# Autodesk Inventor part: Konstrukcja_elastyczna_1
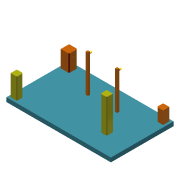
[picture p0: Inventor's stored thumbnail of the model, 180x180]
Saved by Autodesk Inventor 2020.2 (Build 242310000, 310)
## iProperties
Created: 2014-08
Part Number: Konstrukcja_elastyczna_1
Material: Ogólny
Document SubType Name: Modeling
Designer: F.Stasiak
Density: 1 g/cm^3
Appearance: Biały
Catalog Web Link: www.expertbooks.pl
Manager: www.cadconsulting.pl
Company: Fabian Stasiak CAD Consulting
Author: F.Stasiak
Subject: Zbiór ćwiczeń. Autodesk Inventor 2020. Kurs Professional
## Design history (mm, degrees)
sketch "Szkic1"
  geometry: L1 (-1250, 750)-(1250, 750); L2 (1250, 750)-(1250, -750); L3 (1250, -750)-(-1250, -750); L4 (-1250, -750)-(-1250, 750); L5 (-1250, 750)-(1250, -750); L6 (1250, 750)-(-1250, -750); 1 further point
  constraints: 12 end point, 2 midpoint, 2 parallel, 1 horizontal, 1 perpendicular
  dimensions: "d0" = 2500 distance of L2.end L3.end; "d1" = 1500 distance of L1.end L2.end
extrude "Wyciągnięcie proste1" new body sketch "Szkic1" distance "d2" = 100; taper "d3" = 0 deg
sketch "Szkic2"
  geometry: L1 (-1200, -550)-(-1050, -550); L2 (-1050, -550)-(-1050, -700); L3 (-1050, -700)-(-1200, -700); L4 (-1200, -700)-(-1200, -550); L5 (-1200, -550)-(-1050, -700); L6 (-1050, -550)-(-1200, -700); L7 (-1250, -750)-(1250, -750) reference; L8 (-1250, 750)-(-1250, -750) reference; 2 further points
  constraints: 12 end point, 2 midpoint, 2 parallel, 1 horizontal, 1 perpendicular
  dimensions: "d4" = 150 distance of L2.end L3.end; "d5" = 150 distance of L1.end L2.end (= d4); "d6" = 50 distance between parallel lines of L3 L7; "d7" = 50 distance between parallel lines of L8 L4 (= d6)
extrude "Wyciągnięcie proste2" join sketch "Szkic2" distance "d8" = 500; taper "d9" = 0 deg
sketch "Szkic3"
  geometry: L1 (600, -350)-(750, -350); L2 (750, -350)-(750, -200); L3 (750, -200)-(600, -200); L4 (600, -200)-(600, -350); L5 (600, -350)-(750, -200); L6 (750, -350)-(600, -200); L7 (-1250, -750)-(1250, -750) reference; L8 (1250, -750)-(1250, 750) reference; 2 further points
  constraints: 12 end point, 2 midpoint, 2 parallel, 1 horizontal, 1 perpendicular
  dimensions: "d10" = 150 distance of L3.end L2.end; "d11" = 150 distance of L2.end L1.end; "d12" = 400 distance between parallel lines of L7 L1; "d13" = 500 distance between parallel lines of L2 L8
extrude "Wyciągnięcie proste3" join sketch "Szkic3" distance "d14" = 800; taper "d15" = 0 deg
sketch "Szkic4"
  geometry: L1 (-1200, 700)-(-1000, 700); L2 (-1000, 700)-(-1000, 500); L3 (-1000, 500)-(-1200, 500); L4 (-1200, 500)-(-1200, 700); L5 (-1200, 700)-(-1000, 500); L6 (-1000, 700)-(-1200, 500); L7 (-1250, 750)-(-1250, -750) reference; L8 (1250, 750)-(-1250, 750) reference; 2 further points
  constraints: 12 end point, 2 midpoint, 2 parallel, 1 horizontal, 1 perpendicular
  dimensions: "d16" = 200 distance of L2.end L3.end; "d17" = 200 distance of L1.end L2.end; "d18" = 50 distance between parallel lines of L7 L4; "d19" = 50 distance between parallel lines of L8 L1 (= d18)
extrude "Wyciągnięcie proste4" join sketch "Szkic4" distance "d20" = 400; taper "d21" = 0 deg
sketch "Szkic5"
  geometry: L1 (1050, 550)-(1200, 550); L2 (1200, 550)-(1200, 700); L3 (1200, 700)-(1050, 700); L4 (1050, 700)-(1050, 550); L5 (1050, 550)-(1200, 700); L6 (1200, 550)-(1050, 700); L7 (1250, -750)-(1250, 750) reference; L8 (1250, 750)-(-1250, 750) reference; 2 further points
  constraints: 12 end point, 2 midpoint, 2 parallel, 1 horizontal, 1 perpendicular
  dimensions: "d22" = 150 distance of L2.end L3.end; "d23" = 150 distance of L1.end L2.end; "d24" = 50 distance between parallel lines of L7 L2; "d25" = 50 distance between parallel lines of L3 L8 (= d24)
extrude "Wyciągnięcie proste5" join sketch "Szkic5" distance "d26" = 300; taper "d27" = 0 deg
sketch "Szkic6"
  geometry: L1 (400, 300)-(350, 300); L2 (350, 300)-(350, 250); L3 (350, 250)-(400, 250); L4 (400, 250)-(400, 300); L5 (400, 300)-(350, 250); L6 (350, 300)-(400, 250); L7 (1250, 750)-(-1250, 750) reference; L8 (1250, -750)-(1250, 750) reference; 2 further points
  constraints: 12 end point, 2 midpoint, 2 parallel, 1 horizontal, 1 perpendicular
  dimensions: "d28" = 50 distance of L3.end L2.end; "d29" = 50 distance of L2.end L1.end; "d30" = 450 distance between parallel lines of L7 L1; "d31" = 850 distance between parallel lines of L8 L4
extrude "Wyciągnięcie proste6" join sketch "Szkic6" distance "d32" = 900; taper "d33" = 0 deg
node "Płaszczyzna konstrukcyjna1"
sketch "Szkic7"
  geometry: L1 (0, -900)-(0, 0) reference; L2 (50, 0)-(0, 0) reference; L3 (-77.5, -50)-(-65, -50); L4 (-35, -50)-(-22.5, -50); A1 r 15 centre (-50, -50) between (-65, -50) and (-35, -50); A2 r 27.5 centre (-50, -50) between (-77.5, -50) and (-22.5, -50); 1 further point
  constraints: 4 end point, 4 point on circle, 2 centre point, 2 horizontal, 1 coincident
  dimensions: "d34" = 30 diameter of A1; "d35" = 50 distance from line of L2 A1.centre; "d36" = 50 distance from line of L1 A1.centre; "d37" = 55 diameter of A2
extrude "Wyciągnięcie proste7" join sketch "Szkic7" stored distance "d38" = 10; taper "d39" = 0 deg
sketch "Szkic8"
  geometry: L1 (30, -850)-(30, -822.5) reference; L2 (20, -822.5)-(20, -850) reference; L3 (30, -836.25)-(20, -836.25); C1 r 9 at (25, -836.25); 1 further point
  constraints: 3 midpoint, 2 end point, 1 centre point
  dimensions: "d40" = 18 diameter of C1
extrude "Wyciągnięcie proste8" join sketch "Szkic8" distance "d41" = 28; taper "d42" = 0 deg
node "Płaszczyzna konstrukcyjna2"
sketch "Szkic9"
  geometry: L1 (300, 150)-(300, 0) reference; 3 further points
  constraints: 1 horizontal alignment, 1 midpoint
  dimensions: "d52" = 100 distance from line of L1 point (200, 75)
hole "Otwór1" sketch "Szkic9" at (200, 75) diameter "d44" = 18.631; stored, may be unused: countersink angle "d48" = 90 deg, drill point angle "d50" = 118 deg; dims "d45" = 45, "d46" = 4, "d47" = 2, "d49" = 53.5
sketch "Szkic10"
  geometry: L1 (-400, 0)-(-400, 200) reference; 3 further points
  constraints: 1 horizontal alignment, 1 midpoint
  dimensions: "d53" = 100 distance from line of L1 point (-300, 100)
hole "Otwór2" sketch "Szkic10" at (-300, 100) diameter "d54" = 18.631; stored, may be unused: countersink angle "d58" = 90 deg, drill point angle "d60" = 118 deg; dims "d55" = 45, "d56" = 4, "d57" = 2, "d59" = 53.5
sketch "Szkic11"
  geometry: L1 (-500, 0)-(-500, 150) reference; 3 further points
  constraints: 1 horizontal alignment, 1 midpoint
  dimensions: "d61" = 100 distance from line of L1 point (-400, 75)
hole "Otwór3" sketch "Szkic11" at (-400, 75) diameter "d62" = 18.631; stored, may be unused: countersink angle "d66" = 90 deg, drill point angle "d68" = 118 deg; dims "d63" = 45, "d64" = 4, "d65" = 2, "d67" = 53.5
sketch "Szkic12"
  geometry: L1 (0, 800)-(150, 800) reference; 3 further points
  constraints: 1 midpoint, 1 vertical alignment
  dimensions: "d69" = 100 distance from line of L1 point (75, 700)
hole "Otwór4" sketch "Szkic12" at (75, 700) diameter "d70" = 18.631; stored, may be unused: countersink angle "d74" = 90 deg, drill point angle "d76" = 118 deg; dims "d71" = 45, "d72" = 4, "d73" = 2, "d75" = 53.5
node "Punkt konstrukcyjny2"
  node "Płaszczyzna konstrukcyjna3"
  node "Oś konstrukcyjna2"
mirror "Odbicie lustrzane1"
chamfer "Faza1" distance "d77" = 20; stored, may be unused: second distance "d78" = 2, angle "d79" = 45 deg
node "Bryła1"
node "Punkt konstrukcyjny3"
